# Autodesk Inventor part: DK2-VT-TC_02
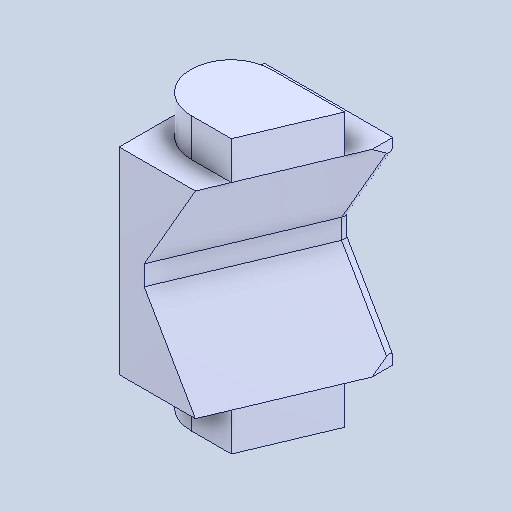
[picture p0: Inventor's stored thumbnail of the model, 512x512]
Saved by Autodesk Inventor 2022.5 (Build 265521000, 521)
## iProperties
Created: 2024-05
Part Number: DK2-VT-TC_02
Material: 一般
Document SubType Name: Modeling
Designer: ImaoCorp
Density: 1 g/cm^3
Appearance: 既定
Author: ImaoCorp
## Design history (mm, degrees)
feature "DK2-VT-TC_02"
node "ソリッド1"
